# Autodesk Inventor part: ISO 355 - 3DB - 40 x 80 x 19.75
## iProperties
IsCustomPart: 0
Created: 2009-02
Part Number: ISO 355 - 3DB - 40 x 80 x 19.75
Material: Steel, Mild
Description: Metric Tapered Roller Bearings
Document SubType Name: Modeling
Standard: ISO 355
Designer: 904Chiaki
Standard Revision: First edition 1977-05-01
Standards Organization: ISO
Language: en-US
Size Designation: 3DB - 40 x 80 x 19.75
Categories: <MemberInstance><Categories><Category DisplayName="Shaft Parts" InternalName="7f7aeb1f-a693-4053-b835-cee3144e0d98" Mnemonic="SHFT"><Category DisplayName="Beari
Density: 1 g/cm^3
Author: 904Chiaki
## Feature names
1. Body [Revolution]
2. Fillet1
3. Roller [Revolution]
4. Rollers [Circular Pattern]
